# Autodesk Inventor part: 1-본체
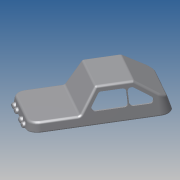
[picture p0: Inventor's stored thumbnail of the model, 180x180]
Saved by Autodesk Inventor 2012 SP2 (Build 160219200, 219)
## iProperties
Created: 2015-05
Part Number: 1-본체
Material: Default
Document SubType Name: Modeling
Designer: Administrator
Density: 1 g/cm^3
Author: Administrator
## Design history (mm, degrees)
sketch "스케치2"
  geometry: L1 (-49, 38)-(49, 38); L2 (61, 26)-(61, -26); L3 (49, -38)-(-49, -38); L4 (-61, -26)-(-61, 26); A1 r 12 centre (-49, 26) between (-49, 38) and (-61, 26); A2 r 12 centre (-49, -26) between (-61, -26) and (-49, -38); A3 r 12 centre (49, -26) between (49, -38) and (61, -26); A4 r 12 centre (49, 26) between (61, 26) and (49, 38); 6 further points
  constraints: 8 end point, 8 point on circle, 8 tangent, 6 point on line, 4 centre point, 3 equal radius, 2 midpoint, 2 parallel, 1 horizontal, 1 horizontal alignment, 1 perpendicular, 1 vertical alignment
  dimensions: "d13" = 122 distance of point (-61, 38) point (61, 38); "d14" = 76 distance of point (-61, -38) point (-61, 38); "d15" = 12 radius of A1
extrude "돌출1" new body sketch "스케치2" distance "d16" = 31; taper "d17" = -15 deg
sketch "스케치3"
  geometry: L1 (-52.694, 31)-(-49, 31) reference; L2 (-49, 0)-(-49, 31) reference; L3 (-49, 0)-(-61, 0) reference; L4 (-61, 0)-(-52.694, 31) reference; L5 (-49, 31)-(49, 31) reference; L6 (49, 0)-(49, 31) reference; L7 (49, 0)-(-49, 0) reference; L8 (-49, 0)-(-49, 31) reference; L9 (49, 31)-(52.694, 31) reference; L10 (61, 0)-(52.694, 31) reference; L11 (61, 0)-(49, 0) reference; L12 (49, 0)-(49, 31) reference; L13 (-58.588, 9)-(-16.588, 9); L14 (-16.588, 9)-(-1.184, 31); L15 (31, 31)-(57.412, 13.392); L16 (61, 0)-(61, 11); L17 (57.412, 13.392)-(61, 11); L18 (-1.184, 31)-(-52.694, 31); L19 (-58.588, 9)-(-52.694, 31); L20 (31, 31)-(52.694, 31); L21 (52.694, 31)-(57.412, 13.392); 1 further point
  constraints: 18 end point, 5 collinear, 4 point on line, 2 perpendicular
  dimensions: "d18" = 9 vertical distance of L13.start L3.end; "d19" = 42 distance of L13.start L13.end; "d20" = 125 deg angle of L14 L13; "d21" = 30 horizontal distance of L15.start L10.start; "d23" = 11 distance of L10.start L16.end
extrude "돌출2" cut sketch "스케치3" stored distance "d24" = 31; taper "d25" = 0 deg
fillet "모깎기1" dims "d26" = 3
fillet "모깎기2" dims "d27" = 3
feature "쉘1" dims "d42" = 2
sketch "스케치7"
  geometry: L1 (2.981, 26)-(20.986, 26); L2 (24.916, 23)-(24.916, 14); L3 (20.986, 11)-(-3.321, 11); L4 (-5.779, 15.721)-(0.523, 24.721); L5 (23.986, 23)-(23.986, 14); L6 (27.916, 11)-(42.078, 11); L7 (43.742, 16.496)-(30.242, 25.496); L8 (28.578, 26)-(27.916, 26); L9 (0.378, 31)-(30.092, 31) reference; L10 (-15.693, 10.279)-(-2.08, 29.721) reference; L11 (31.756, 30.496)-(50.664, 17.891) reference; A1 r 3 centre (2.981, 23) between (2.981, 26) and (0.523, 24.721); A2 r 3 centre (-3.321, 14) between (-5.779, 15.721) and (-3.321, 11); A3 r 3 centre (20.986, 14) between (20.986, 11) and (23.986, 14); A4 r 3 centre (20.986, 23) between (23.986, 23) and (20.986, 26); A5 r 3 centre (27.916, 23) between (27.916, 26) and (24.916, 23); A6 r 3 centre (27.916, 14) between (24.916, 14) and (27.916, 11); A7 r 3 centre (42.078, 14) between (42.078, 11) and (43.742, 16.496); A8 r 3 centre (28.578, 23) between (30.242, 25.496) and (28.578, 26); 11 further points
  constraints: 16 end point, 16 point on circle, 16 tangent, 13 point on line, 8 centre point, 7 equal radius, 4 midpoint, 4 parallel, 3 perpendicular, 2 horizontal alignment, 1 horizontal
  dimensions: "d43" = 15 distance of point (24.916, 26) point (24.916, 11); "d44" = 5 distance between parallel lines of L1 L9; "d45" = 5 distance between parallel lines of L7 L11; "d46" = 5 distance between parallel lines of L10 L4; "d49" = 34 distance of point (24.916, 11) point (-9.084, 11); "d50" = 28 distance of point (23.986, 11) point (51.986, 11); "d51" = 3 radius of A1
extrude "돌출5" cut sketch "스케치7" stored distance "d52" = 1; taper "d53" = 0 deg
sketch "스케치8"
  geometry: L1 (61, 26)-(61, -26) reference; L2 (-49, 38)-(49, 38) reference; L3 (-61, -26)-(-61, 26) reference; L4 (49, -38)-(-49, -38) reference; L5 (60, 26)-(60, -26); L6 (49, -37)-(-49, -37); L7 (-60, -26)-(-60, 26); L8 (-49, 37)-(49, 37); A1 r 12 centre (49, 26) between (61, 26) and (49, 38) reference; A2 r 12 centre (-49, 26) between (-49, 38) and (-61, 26) reference; A3 r 12 centre (-49, -26) between (-61, -26) and (-49, -38) reference; A4 r 12 centre (49, -26) between (49, -38) and (61, -26) reference; A5 r 11 centre (49, 26) between (60, 26) and (49, 37); A6 r 11 centre (49, -26) between (49, -37) and (60, -26); A7 r 11 centre (-49, -26) between (-60, -26) and (-49, -37); A8 r 11 centre (-49, 26) between (-49, 37) and (-60, 26); 1 further point
  constraints: 8 end point, 8 point on circle, 4 centre point, 7 other
  dimensions: "d54" = 1 distance between parallel lines of L2 L8
extrude "돌출6" cut sketch "스케치8" distance "d55" = 1; taper "d56" = 0 deg
node "작업 평면1"
sketch "스케치9"
  geometry: A1 r 4 centre (-21, 1) between (-17, 1) and (-25, 1); A2 r 4 centre (-10, 1) between (-6, 1) and (-14, 1); A3 r 4 centre (10, 1) between (14, 1) and (6, 1); A4 r 4 centre (21, 1) between (25, 1) and (17, 1); 4 further points; 1 other entity
  constraints: 8 point on circle, 4 centre point, 4 horizontal alignment, 10 other
  dimensions: "d58" = 8 diameter of A1; "d59" = 8 diameter of A2; "d60" = 8 diameter of A3; "d61" = 8 diameter of A4; "d62" = 20 distance of A2.centre A3.centre; "d63" = 11 distance of A4.centre A3.centre; "d64" = 11 distance of A2.centre A1.centre; "d65" = 10 horizontal distance of A2.centre point (0, 0)
extrude "돌출7" join sketch "스케치9" stored distance "d66" = 4; taper "d67" = 0 deg
chamfer "모따기1" distance "d68" = 1; stored, may be unused: second distance "d69" = 2, angle "d70" = 45 deg
node "솔리드1"
node "투영된 루프1"
node "투영된 루프2"
node "투영된 루프3"
other parameters: "d57" = 61
